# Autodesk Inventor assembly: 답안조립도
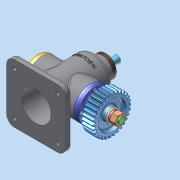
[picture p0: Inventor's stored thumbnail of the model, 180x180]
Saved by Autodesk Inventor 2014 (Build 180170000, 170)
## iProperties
Created: 2026-06
Part Number: 답안조립도
Document SubType Name: Assembly
Designer: dg
Author: dg
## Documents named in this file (17)
- C:\Users\dg\Desktop\660603V1003\답안조립도.iam
- C:\Users\dg\Desktop\660603V1003\가져온 구성요소\본체\본체.ipt
- C:\Users\dg\Desktop\660603V1003\가져온 구성요소\6각 구멍붙이 볼트 M3x8\6각 구멍붙이 볼트 M3x8.ipt
- C:\Users\dg\Desktop\660603V1003\가져온 구성요소\6각 구멍붙이 볼트 M4x8\6각 구멍붙이 볼트 M4x8.ipt
- C:\Users\dg\Desktop\660603V1003\가져온 구성요소\6각 너트 M10x1\6각 너트 M10x1.ipt
- C:\Users\dg\Desktop\660603V1003\가져온 구성요소\가이드 부시\가이드 부시.ipt
- C:\Users\dg\Desktop\660603V1003\가져온 구성요소\깊은 홈 볼 베어링 6003\깊은 홈 볼 베어링 6003.ipt
- C:\Users\dg\Desktop\660603V1003\가져온 구성요소\뒷 커버\뒷 커버.ipt
- C:\Users\dg\Desktop\660603V1003\가져온 구성요소\스퍼 기어\스퍼 기어.ipt
- C:\Users\dg\Desktop\660603V1003\가져온 구성요소\스프링 와셔 M10\스프링 와셔 M10.ipt
- C:\Users\dg\Desktop\660603V1003\가져온 구성요소\슬라이더\슬라이더.ipt
- C:\Users\dg\Desktop\660603V1003\가져온 구성요소\앞 커버\앞 커버.ipt
- C:\Users\dg\Desktop\660603V1003\가져온 구성요소\오일 실 17 30 8\오일 실 17 30 8.ipt
- C:\Users\dg\Desktop\660603V1003\가져온 구성요소\캠 축\캠 축.ipt
- C:\Users\dg\Desktop\660603V1003\가져온 구성요소\평와셔 M10\평와셔 M10.ipt
- C:\Users\dg\Desktop\660603V1003\가져온 구성요소\평행 키 3x3x14\평행 키 3x3x14.ipt
- C:\Users\dg\Desktop\660603V1003\가변스프링.ipt
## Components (15 placed, 5 different names)
1. 6각 너트 M10x1:1
2. 가이드 부시:1
3. 가변스프링:1
4. 6각 구멍붙이 볼트 M4x8:2
5. 6각 구멍붙이 볼트 M4x8:3
6. 6각 구멍붙이 볼트 M4x8:4
7. 6각 구멍붙이 볼트 M4x8:5
8. 6각 구멍붙이 볼트 M4x8:1
9. 6각 구멍붙이 볼트 M4x8:6
10. 6각 구멍붙이 볼트 M4x8:7
11. 6각 구멍붙이 볼트 M4x8:8
12. 6각 구멍붙이 볼트 M3x8:1
13. 6각 구멍붙이 볼트 M3x8:2
14. 6각 구멍붙이 볼트 M3x8:3
15. 6각 구멍붙이 볼트 M3x8:4
